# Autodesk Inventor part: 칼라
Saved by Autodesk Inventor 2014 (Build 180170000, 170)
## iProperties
Created: 2026-05
Part Number: 칼라
Material: 일반
Document SubType Name: Modeling
Designer: dg
Density: 1 g/cm^3
Appearance: 기본값
Author: dg
Author: jhkim
Creation Date: 2026-04-23
Sending System: Autodesk Inventor 2027
Preprocessor: ST-DEVELOPER v20.1
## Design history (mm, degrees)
node "칼라1"
node "솔리드1"
node "기준1"
